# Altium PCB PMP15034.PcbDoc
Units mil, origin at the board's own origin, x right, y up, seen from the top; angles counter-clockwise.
Board outline 1900.05 x 1702.97 mil, 2 copper layers (Top Layer, Bottom Layer), stack 62 mil thick; 32 components, 19 nets, 82 pads, 10 vias.
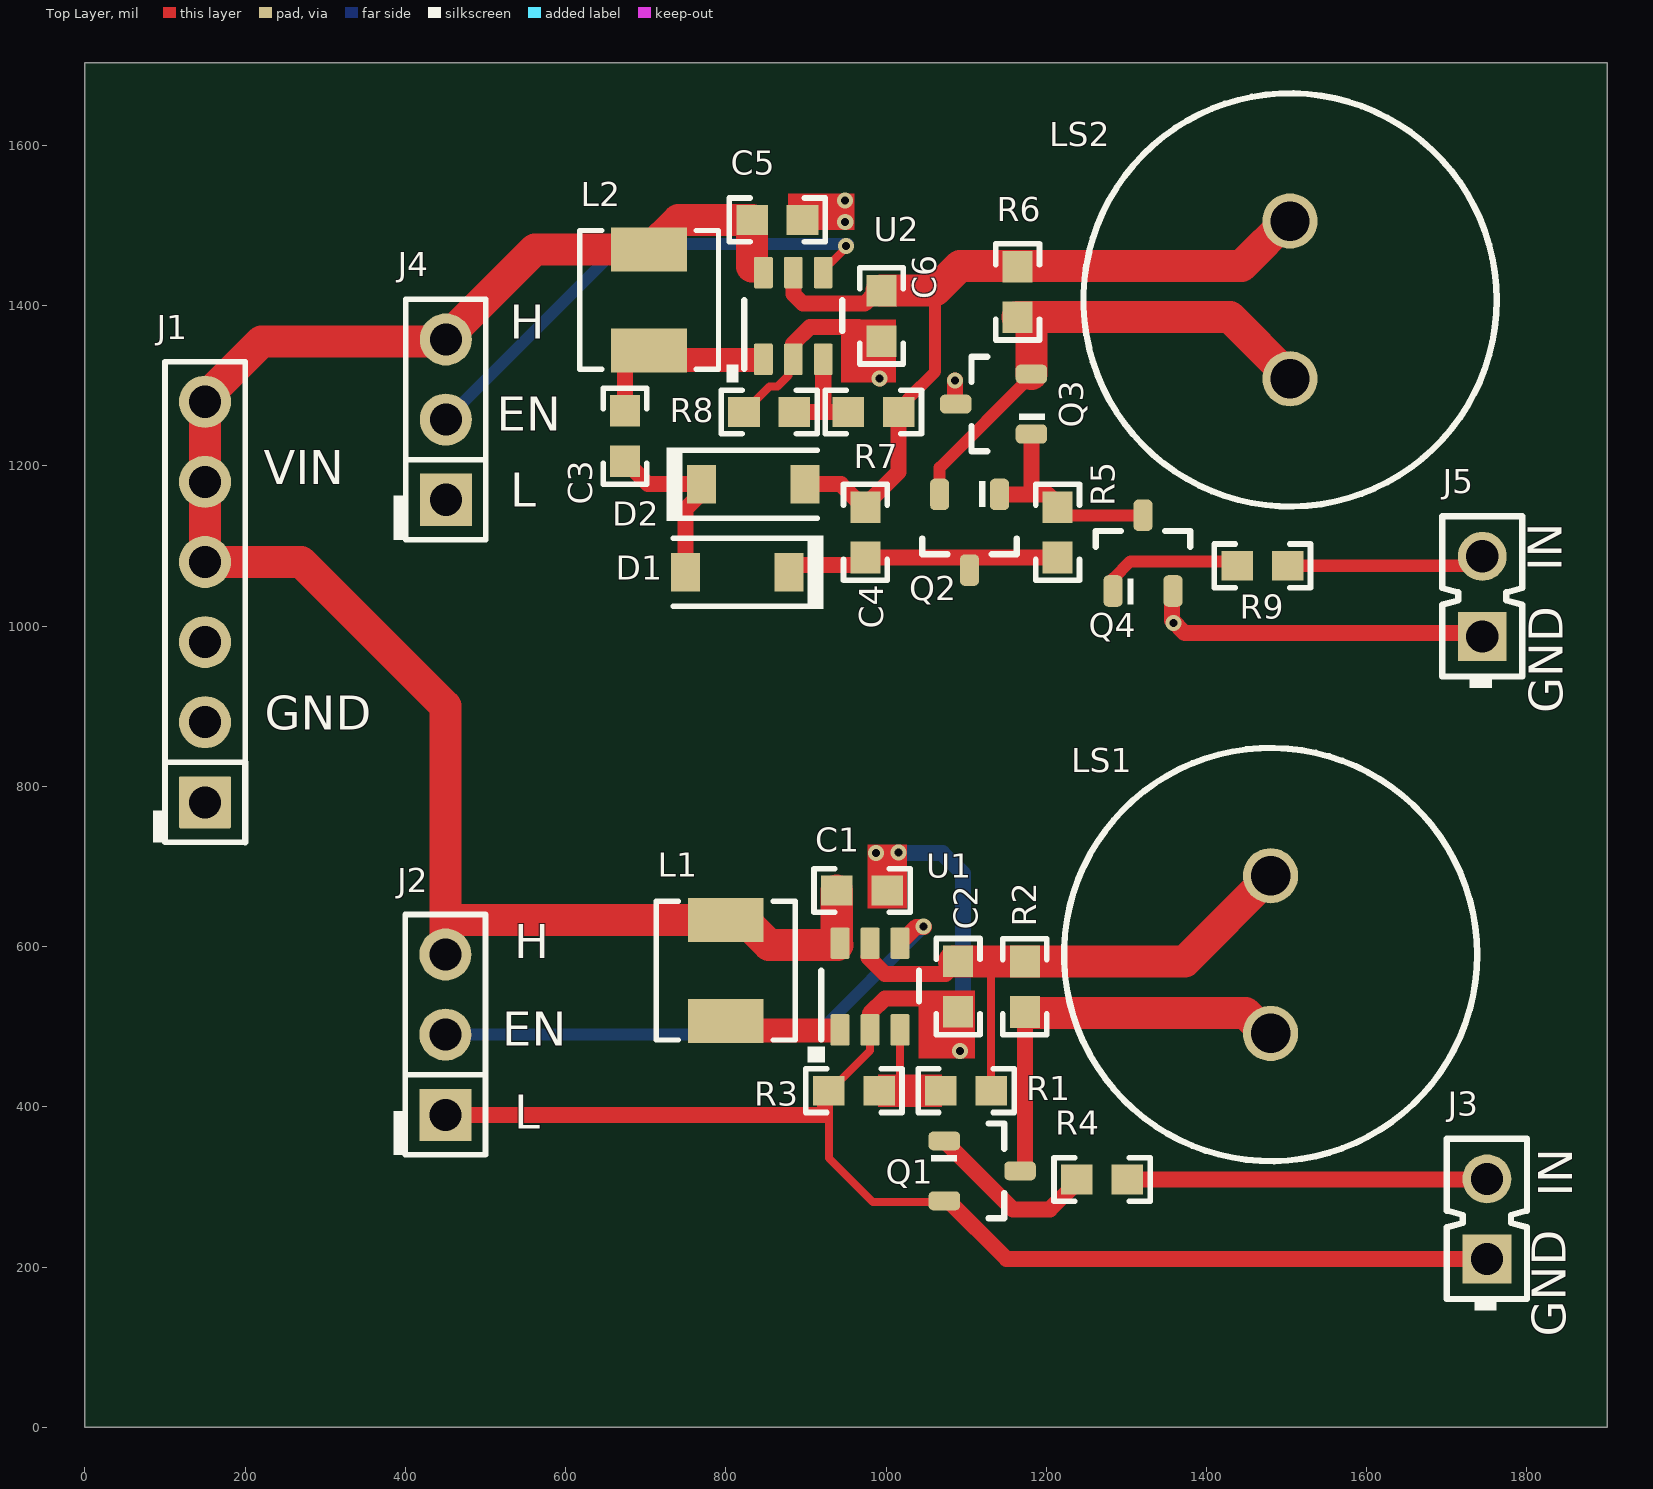
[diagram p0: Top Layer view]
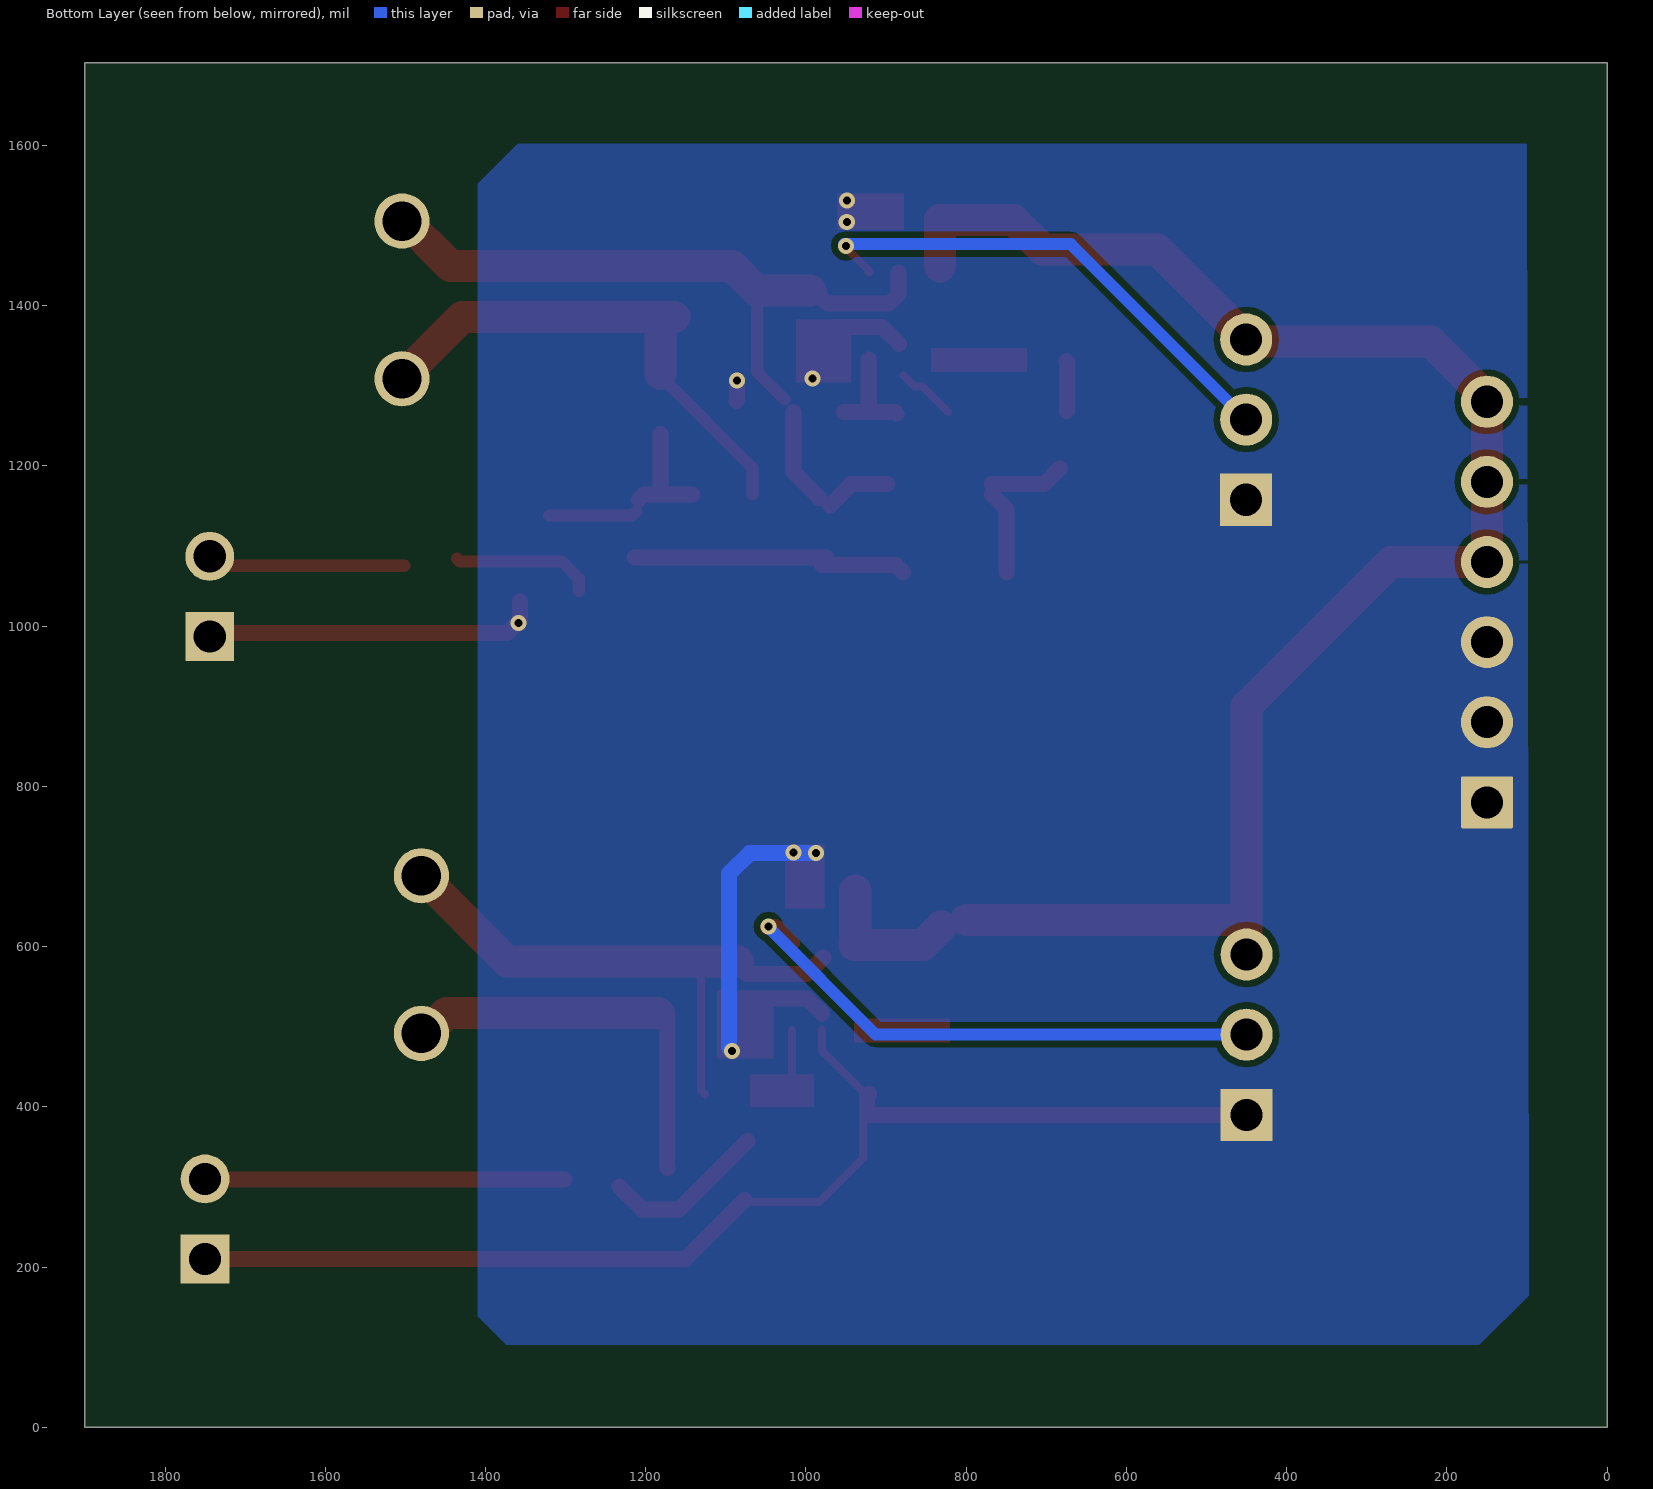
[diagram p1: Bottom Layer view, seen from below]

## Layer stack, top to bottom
Top Solder: solder mask 0.4, Solder Resist, Dk 3.5
Top Layer: signal copper 1.4
Dielectric1: core 59.2, FR-4, Dk 4.8
Bottom Layer: signal copper 1.4
Bottom Solder: solder mask 0.4, Solder Resist, Dk 3.5

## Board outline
0,0 1900,0 1899.96,1702.97 1900.05,1702.81 0.05,1702.81 0,1702.78

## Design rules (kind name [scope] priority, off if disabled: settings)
AcuteAngle [All] p1: minimum=4.50000000000000E+0001 checktracksonly=FALSE
AssemblyTestPointUsage [All] p1: valid=2
Clearance "U1 Clearance" [InComponent('U1')] p1: gap=4
Clearance "U2 Clearance" [InComponent('U2')] p2: gap=4
Clearance Clearance_BoardEdge_MountingHoles [OnCopper and InComponentClass('Mounting Holes') vs IsKeepOut] p3: gap=3.94
Clearance Clearance_BoardEdge_Poly [OnCopper and InPoly vs IsKeepOut] p4: gap=10
Clearance Clearance_BoardEdge [OnCopper and Not InComponentClass('Logo') and not InComponentClass('FiducialMark') and not InRegion(1000,500,4000,800) vs IsKeepOut] p5: gap=30
Clearance [All] p6: gap=8
ComponentClearance ComponentClearance_SHUNT [InComponentClass('Shunt')] p1: gap=0 collisioncheckmode=3 verticalgap=0 showdistances=FALSE
ComponentClearance ComponentClearance_Logo [All] p2: gap=10 collisioncheckmode=3 verticalgap=10 showdistances=FALSE
ComponentClearance ComponentClearance_ScrewToNut [(HasFootprint('NY PMS 440 0025 PH')) vs (HasFootprint('Keystone_1902C'))] p3: gap=5 collisioncheckmode=3 verticalgap=10 showdistances=FALSE
ComponentClearance ComponentClearance_MountingHoles [InComponentClass('Mounting Holes')] p4: gap=250 collisioncheckmode=3 verticalgap=100000 showdistances=FALSE
ComponentClearance ComponentClearance_SmallPassives [HasFootprint('0201*') or HasFootprint('0402*') or HasFootprint('0508') or HasFootprint('0603*') or HasFootprint('0612') or HasFootprint('0805*') or HasFootprint('0815*') or HasFootprint('0830*') or HasFootprint('1206*') or HasFootprint('1210*') or HasFootprint('1808*') or HasFootprint('1812*') or HasFootprint('1825*') or HasFootprint('2010*') or HasFootprint('2220*') or HasFootprint('2225*') or HasFootprint('2512*') or HasFootprint('2728*') or HasFootprint('3518*') vs HasFootprint('0201*') or HasFootprint('0402*') or HasFootprint('0508') or HasFootprint('0603*') or HasFootprint('0612') or HasFootprint('0805*') or HasFootprint('0815*') or HasFootprint('0830*') or HasFootprint('1206*') or HasFootprint('1210*') or HasFootprint('1808*') or HasFootprint('1812*') or HasFootprint('1825*') or HasFootprint('2010*') or HasFootprint('2220*') or HasFootprint('2225*') or HasFootprint('2512*') or HasFootprint('2728*') or HasFootprint('3518*')] p5: gap=20 collisioncheckmode=3 verticalgap=10 showdistances=FALSE
ComponentClearance ComponentClearance_THtoSMT [IsThruComponent vs IsSMTComponent] p6 off: gap=10 collisioncheckmode=3 verticalgap=100000 showdistances=FALSE
ComponentClearance ComponentClearance_THtoTH [IsThruComponent vs IsThruComponent] p7: gap=10.11 collisioncheckmode=3 verticalgap=100000 showdistances=FALSE
ComponentClearance [All] p8: gap=10 collisioncheckmode=3 verticalgap=10 showdistances=FALSE
DiffPairsRouting [All] p1: maxlimit=100 minlimit=10 mostfreqgap=10 toplayer_minwidth=15 toplayer_maxwidth=15 toplayer_prefwidth=15 bottomlayer_minwidth=15 bottomlayer_maxwidth=15 bottomlayer_prefwidth=15 maxuncoupledlength=1000
FabricationTestPointUsage TestPointUsage [All] p1: valid=2 allowmultiple=FALSE
FabricationTestpoint Testpoint [All] p1: side=3 testpointundercomponent=TRUE minsize=40 maxsize=100 preferedsize=60 minholesize=0 maxholesize=40 preferedholesize=32 testpointgrid=1 allowsidetop=TRUE allowsidebottom=TRUE usegrid=TRUE gridtolerance=0.01
FanoutControl Fanout_LCC [IsLCC] p1: bgadir=Out bgaviamode=Centered fanoutstyle=Auto fanoutdirection=Alternating viagrid=1 // Fanout_LCC (Default Rule)
FanoutControl Fanout_BGA [IsBGA] p2: bgadir=Out bgaviamode=Centered fanoutstyle=Auto fanoutdirection=Alternating viagrid=1 // Fanout_BGA (Default Rule)
FanoutControl Fanout_Default [All] p4: bgadir=Out bgaviamode=Centered fanoutstyle=Auto fanoutdirection=Alternating viagrid=1 // Fanout_Default (Default Rule)
FanoutControl Fanout_Small [(CompPinCount < 5)] p5: bgadir=Out bgaviamode=Centered fanoutstyle=Auto fanoutdirection=OutThenIn viagrid=1 // Fanout_Small (Default Rule)
HoleSize [All] p1: absolutevalues=TRUE maxlimit=180 minlimit=8 maxpercent=80.000 minpercent=20.000
HoleToHoleClearance [All] p1: gap=1 allowstackedmicrovias=TRUE
MinimumAnnularRing MinimumAnnularRing_small [TouchesRoom('BGA_Room')] p1: minimumring=2.8
MinimumAnnularRing [All] p2: minimumring=5
MinimumSolderMaskSliver U2 [InComponent('U1')] p1: minsoldermaskwidth=3
MinimumSolderMaskSliver "SW PIN" [InNet('SW')] p2: minsoldermaskwidth=10
MinimumSolderMaskSliver U1 [InComponent('U2')] p3: minsoldermaskwidth=3
MinimumSolderMaskSliver SilkscreenOverComponentPads [All] p4: minsoldermaskwidth=5
MinimumSolderMaskSliver MinimumSolderMaskSliver_Logo [InComponentClass('Logo') vs InComponentClass('Logo')] p5: minsoldermaskwidth=0.7
MinimumSolderMaskSliver [All] p6: minsoldermaskwidth=4
PlaneClearance [All] p1: clearance=10
PlaneConnect [All] p1: planeconnectstyle=Direct reliefexpansion=10 reliefentries=4 reliefconductorwidth=10 reliefairgap=10
PolygonConnect PolygonConnect-TH-Relief [IsPoly vs (IsThruPin)  And Not (InComponent('U3'))  And Not (InComponent('U4'))] p1: connectstyle=Direct reliefconductorwidth=20 reliefentries=4 polygonreliefangle="90 Angle" airgapwidth=10
PolygonConnect PolygonConnect-DirectConn [All] p2: connectstyle=Direct reliefconductorwidth=10 reliefentries=4 polygonreliefangle="90 Angle" airgapwidth=10
RoutingVias [All] p1: holewidth=10 width=22 viastyle="Through Hole" minholewidth=4 minwidth=10 maxholewidth=50 maxwidth=100
SMDToCorner [All] p1: distance=0
SilkToBoardRegionClearance [Not ((IsComment or IsDesignator) And (Hide <> 'False')) and not InRegion(1000,500,4000,800)] p1:
SilkToSilkClearance "Pb Free Logo" [(HasFootprint('Pb-Free_Overlay_Medium') OR HasFootprint('Pb-Free_Overlay_Small')) vs (HasFootprint('Pb-Free_Overlay_Medium') OR HasFootprint('Pb-Free_Overlay_Small'))] p1: silktosilkclearance=0
SilkToSilkClearance [All] p2: silktosilkclearance=3
SilkToSolderMaskClearance [IsPad] p1: minsilkscreentomaskgap=4 clearancetoexposedcopper=TRUE
SolderMaskExpansion [All] p1: expansion=1
Width [All] p1: maxlimit=100 minlimit=6 preferedwidth=10 checkconnectedcopper=TRUE
13 further rules are at their usual default settings.

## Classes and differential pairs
component class Header: J1 J2 J3 J4 J5

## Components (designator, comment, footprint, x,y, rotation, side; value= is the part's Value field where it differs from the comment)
C1 "GRM188R60J475KE19D" 0603 970,670 r0 top
C2 "GRM188R6YA475KE15D" 0603 1090,550 r270 top
C3 "GRM188R71H104KA93D" 0603 674.22,1237.06 r270 top
C4 "GRM188R6YA475KE15D" 0603 974.22,1117.06 r90 top
C5 "GRM188R60J475KE19D" 0603 864.22,1507.06 r0 top
C6 "GRM188R6YA475KE15D" 0603 994.22,1387.06 r270 top
D1 "1N4148W-7-F" SOD-123 814.22,1067.06 r180 top
D2 "1N4148W-7-F" SOD-123 834.22,1177.06 r0 top
J1 "TSW-106-07-G-S" TSW-106-07-G-S 150,1030 r90 top
J2 "TSW-103-07-G-S" TSW-103-07-G-S 450,490 r90 top
J3 "TSW-102-07-T-S" Samtec_TSW-102-07-T-S 1750,260 r90 top
J4 "TSW-103-07-G-S" TSW-103-07-G-S 450.49,1257.68 r90 top
J5 "TSW-102-07-T-S" Samtec_TSW-102-07-T-S 1744.22,1037.06 r90 top
L1 "FDSD0420-H-100M" FDSD0420 800,570 r270 top
L2 "FDSD0420-H-100M" FDSD0420 704.22,1407.06 r270 top
LS1 "PKM13EPYH4002-B0" MuRata_PKM13 1480,590 r270 top
LS2 "PKM13EPYH4002-B0" MuRata_PKM13 1504.22,1407.06 r90 top
Q1 "MMBT3904-7-F" SOT-23 1120,320 r0 top
Q2 "MMBT3904-7-F" SOT-23 1104.22,1117.06 r270 top
Q3 "MMBT3906-7-F" SOT-23 1134.22,1277.06 r180 top
Q4 "MMBT3904-7-F" SOT-23 1320.78,1091.03 r90 top
R1 "CRCW06031M00FKEA" 0603 1100,420 r0 top
R2 "CRCW06033K01FKEA" 0603 1173.18,549.8 r90 top
R3 "CRCW060329K4FKEA" 0603 960,420 r0 top
R4 "CRCW060310K0FKEA" 0603 1269.65,309.33 r0 top
R5 "CRCW060310K0FKEA" 0603 1214.22,1117.06 r90 top
R6 "CRCW06031M00FKEA" 0603 1164.22,1417.06 r270 top
R7 "CRCW06031M00FKEA" 0603 984.22,1267.06 r0 top
R8 "CRCW060356K2FKEA" 0603 854.22,1267.06 r0 top
R9 "CRCW060310K0FKEA" 0603 1469.81,1075.28 r180 top
U1 "TLV61046ADBVR" DBV0006A_N 980,550 r90 top
U2 "TLV61046ADBVR" DBV0006A_N 884.22,1387.06 r90 top

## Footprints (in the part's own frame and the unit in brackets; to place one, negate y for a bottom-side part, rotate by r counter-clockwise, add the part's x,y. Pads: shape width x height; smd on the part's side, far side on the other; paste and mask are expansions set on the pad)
0603 [mm] "0603 from SM-752 data"
  rect 1x0.95 smd: 1(-0.8,0) 2(0.8,0)
  silkscreen extent -1.52,-0.69 1.52,0.69, body extent -0.87,-0.47 0.87,0.47, height 1
DBV0006A_N [mm] "SOT23, 6-Leads, Body 2.9x1.6mm, Pitch 0.95mm, Lead Span 2.8mm, IPC Medium Density"
  rrect17% 1x0.6 smd: 1(-1.375,0.95) 2(-1.375,0) 3(-1.375,-0.95) 4(1.375,-0.95) 5(1.375,0) 6(1.375,0.95)
  silkscreen extent -1.68,-1.55 0.5,1.55, body extent -1.42,-1.46 1.42,1.46, height 1.12
FDSD0420 [mm] "SMD, 2-Leads, Body 4.2x4.2mm"
  rect 1.4x2.4 smd: 1(-1.6,0) 2(1.6,0)
  silkscreen extent -2.2,-2.2 2.2,2.2, body extent -2.1,-2.1 2.1,2.1, height 2
MuRata_PKM13 [mm] "TH, 2-Leads, Dia 12.6mm, Pitch 5mm"
  round 1.75 hole 1.25: 1(-2.5,0) 2(2.5,0)
  silkscreen extent -6.55,-6.55 6.55,6.55, body extent -6.55,-6.55 6.55,6.55, height 7.4
Samtec_TSW-102-07-T-S [mm] "Header, 2.54 mm, 2x1, Tin, TH"
  rect 1.55x1.55 hole 1.02: 1(-1.27,0)
  round 1.55 hole 1.02: 2(1.27,0)
  silkscreen extent -2.9,-1.27 2.54,1.27, body extent -2.54,-1.27 2.54,1.27, height 8.38
SOD-123 [mm] "On Semi recommended land pattern"
  rect 0.915x1.22 smd: 1(-1.637,0) 2(1.637,0)
  silkscreen extent -2.74,-1.17 2.03,1.17, body extent -1.93,-0.9 1.93,0.9, height 1.35
SOT-23 [mm] "SOT23, 3-Leads, Body 2.9x1.3mm, Pitch 0.95mm, Lead Span 2.5mm, IPC Medium Density"
  rrect50% 1x0.6 smd: 1(-1.2,0.95) 2(-1.2,-0.95) 3(1.2,0)
  silkscreen extent -1.63,-1.5 0.7,1.5, body extent -1.16,-1.45 1.21,1.45, height 1
TSW-103-07-G-S [mm] "Samtec 100mil, 1x3, 230 mil above insulator"
  rect 1.65x1.65 hole 1.016: 1(-2.54,0)
  round 1.65 hole 1.016: 2(0,0) 3(2.54,0)
  silkscreen extent -3.81,-1.27 3.81,1.65, body extent -3.81,-1.27 3.81,1.27, height 8.38
TSW-106-07-G-S [mm] "Samtec 100mil, 1x6, 230 mil above insulator"
  rrect6% 1.65x1.65 hole 1.016: 1(-6.35,0)
  round 1.65 hole 1.016: 2(-3.81,0) 3(-1.27,0) 4(1.27,0) 5(3.81,0) 6(6.35,0)
  silkscreen extent -7.62,-1.27 7.62,1.65, body extent -7.62,-1.27 7.62,1.27, height 8.38

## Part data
C1 C5: "CAP, CERM, 4.7 µF, 6.3 V, +/- 10%, X5R, 0603"
C2 C4 C6: "CAP, CERM, 4.7 µF, 35 V, +/- 10%, X5R, 0603"
C3: "CAP, CERM, 0.1 µF, 50 V, +/- 10%, X7R, 0603"
D1 D2: "Diode, Ultrafast, 100 V, 0.15 A, SOD-123"
J1: "Header, 100mil, 6x1, Gold, TH"
J2 J4: "Header, 100mil, 3x1, Gold, TH"
J3 J5: "Header, 2.54 mm, 2x1, Tin, TH"
L1 L2: "Inductor, Shielded, Powdered Iron, 10 µH, 2 A, 0.2 ohm, SMD"
LS1 LS2: "Buzzer, 4 kHz, 12.6mm Dia, TH"
Q1 Q2 Q4: library part "MMBT3904-7-F, Diodes Inc.", "Transistor, NPN, 40 V, 0.2 A, SOT-23"
Q3: library part "MMBT3906-7-F, Diodes Inc.", "Transistor, PNP, 40 V, 0.2 A, SOT-23"
R1 R6 R7: "RES, 1.00 M, 1%, 0.1 W, 0603"
R2: "RES, 3.01 k, 1%, 0.1 W, 0603"
R3: "RES, 29.4 k, 1%, 0.1 W, 0603"
R4 R5 R9: "RES, 10.0 k, 1%, 0.1 W, 0603"
R8: "RES, 56.2 k, 1%, 0.1 W, 0603"
U1 U2: "28-V Output Voltage Boost Converter with Power Diode and Isolation Switch, DBV0006A (SOT-6)"

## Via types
v1: diameter 20, hole 10, Top Layer to Bottom Layer, 10 vias

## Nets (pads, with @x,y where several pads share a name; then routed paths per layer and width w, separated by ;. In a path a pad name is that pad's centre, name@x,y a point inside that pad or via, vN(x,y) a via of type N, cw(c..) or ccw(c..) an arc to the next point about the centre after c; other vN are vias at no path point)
15V: C4.2 C6.1 D2.2 LS2.2 R6.1 R7.2 U2.5 | length 1040.5
  Top Layer w15: R7.2@1026.57,1282.72 1061.33,1317.48 1061.33,1418.56
  Top Layer w20: U2.5 884.22,1414.48 896.36,1402.34 973.21,1402.34 C6.1@985.47,1414.6 ; D2.2 943.58,1177.06 C4.2@970.25,1150.38 ; C4.2@983.44,1160.1 1015.72,1192.38 R7.2
  Top Layer w40: C6.1 1061.33,1418.56 1092.11,1449.34 1443.78,1449.34 LS2.2@1505.23,1510.8
28V: C2.1 LS1.1 R1.2 R2.2 U1.5 | length 803
  Top Layer w10: R1.2@1126.14,415.58 1131.21,420.66 1131.21,581.5
  Top Layer w20: U1.5@978.19,586.1 998.81,565.48 1073.98,565.48 C2.1 1131.21,581.5 R2.2@1160,581.5
  Top Layer w40: C2.1@1084.94,581.29 1372.84,581.5 LS1.1@1478.99,687.65
30V: C4.1 D1.1 Q2.3 R5.1 | length 345.1
  Top Layer w20: D1.1 887.8,1076.17 C4.1@979.99,1076.17 ; C4.1 R5.1
ENA: J2.2 U1.4 | length 693.6
  Top Layer w20: U1.4 1037.79,624.52 v1@1047.65,624.52
  Bottom Layer w15: J2.2 912.88,490 v1@1048.64,625.76
  other v1: 1046.81,624.94
ENB: J4.2 U2.4 | length 637.9
  Top Layer w10: U2.4 921.62,1443.86 v1@951.7,1473.94
  Bottom Layer w15: J4.2 669.4,1476.59 v1@952.5,1476.59
  other v1: 950.05,1474.43
FBA: R1.1 R3.2 U1.3 | length 83.3
  Top Layer w10: 1017.4,412.58 U1.3
FBB: R7.1 R8.2 U2.3 | length 129.7
  Top Layer w20: R8.2@886.84,1265.57 888.33,1267.06 R7.1 ; 921.62,1269.77 U2.3
GND: C1.2 C2.2 C5.2 C6.2 J1.1 J1.2 J1.3 J2.1 J3.1 J4.1 J5.1 Q1.2 Q3.3 Q4.2 R3.1 R8.1 U1.2 U2.2 | length 2737.9
  Top Layer w10: R8.1 854.71,1299.05 864.68,1299.05 878.43,1312.8 ; U1.2 980,470 930,420 R3.1 928.5,336.12 983.5,281.12 Q1.2@1066.1,281.12
  Top Layer w20: J2.1 923.74,390 923.74,413.45 R3.1@921.53,415.66 ; U2.2@883.88,1352.2 905.12,1373.44 965.54,1373.44 983.41,1355.57 C6.2 994.22,1310.63 v1@992.72,1309.13 ; 979.91,516.51 998.81,535.41 1065.25,535.41 1082.15,518.5 C2.2 ; Q1.2@1076.54,283.83 1150.37,210 J3.1 ; v1(1085.92,1306.6) 1085.92,1282.08 Q3.3@1086.8,1281.2 ; C2.2@1090,516.35 1092.1,514.25 v1(1092.1,469.81) ; Q4.2@1357.18,1030.76 1357.03,1030.62 1357.03,1006.97 1372.84,991.16 J5.1@1734.9,991.16
  Bottom Layer w20: v1(987.51,716.71) 1070.37,716.71 1096.15,690.93 v1@1096.15,473.69
  other v1: 1015.74,717.59 1358.59,1003.8 991.76,1309.13 949.08,1504.44 948.81,1531.46
NetC3_1: C3.1 L2.2 U2.1 | length 62.9
  Top Layer w20: C3.1 674.22,1330.23 L2.2@675.08,1331.09
NetC3_2: C3.2 D1.2 D2.1 | length 197.1
  Top Layer w20: C3.2@683.05,1196.91 702.9,1177.06 D2.1@767.53,1177.06 ; D1.2 749.75,1146.28 D2.1@767.53,1164.06
NetJ3_2: J3.2 R4.2 | length 465.3
  Top Layer w20: R4.2 J3.2@1766.45,309.33
NetJ5_2: J5.2 R9.1 | length 255.5
  Top Layer w15: R9.1 J5.2@1756.82,1075.28
NetL1_2: L1.2 U1.1
NetLS1_2: LS1.2 Q1.3 R2.1 | length 498.1
  Top Layer w20: Q1.3@1173.1,323.84 1173.18,323.93 R2.1
  Top Layer w40: R2.1@1183.78,517.04 1448.48,517.04 LS1.2@1476.01,489.51
NetLS2_1: LS2.1 Q2.2 Q3.2 R6.2 | length 629.4
  Top Layer w15: Q2.2 1066.82,1197.65 Q3.2@1182.19,1313.03
  Top Layer w40: R6.2 1429.4,1385.57 LS2.1@1502.04,1312.92 ; R6.2@1177.82,1377.97 1181.46,1374.32 Q3.2
NetQ1_1: Q1.1 R4.1 | length 207.2
  Top Layer w20: Q1.1 1158.22,271.94 1204.35,271.94 R4.1@1232.81,300.4
NetQ2_1: Q2.1 Q3.1 Q4.3 R5.2 | length 253.4
  Top Layer w15: R5.2@1211.64,1143.23 1216.6,1138.27 Q4.3
  Top Layer w20: Q2.1 1202.02,1164.31 R5.2@1208.12,1158.21 ; 1181.46,1166.46 Q3.1
NetQ4_1: Q4.1 R9.2 | length 177.8
  Top Layer w15: Q4.1 1283.38,1059.1 1305,1080.72 1432.2,1080.72 R9.2@1435.53,1084.05
VIN: C1.1 C5.1 J1.4 J1.5 J1.6 J2.3 J4.3 L1.1 L2.1 U1.6 U2.6 | length 2252.5
  Top Layer w40: J1.6@150,1290 J1.6 J1.5 J1.4 270,1080 450,900 J2.3 ; J1.6@153.03,1287.81 220.44,1355.21 446.78,1355.21 561.63,1470.05 L2.1 741.23,1507.06 C5.1 832.72,1448.56 ; 457.01,632.99 L1.1 ; L1.1@831.27,624.76 853.9,602.13 939.53,602.13 938.5,603.15 C1.1

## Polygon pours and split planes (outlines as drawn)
GND on Bottom Layer "BOTTOM_LAYER_GND_P000" (solid, remove dead copper, pour order 0): 100.25,1601.79 1359.79,1601.79 1409.6,1551.98 1409.6,138.27 1374.02,102.69 159.55,102.69 97.88,164.36

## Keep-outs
Keep-Out Layer:
  text ".Layer_Name" at 577,-858.49 h60

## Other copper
Top Layer:
  rectangle net GND: 943.69,1303.93 1012.38,1382.85
  rectangle net GND: 1040.8,460.03 1111.31,545.29
  rectangle net GND: 976.57,647.46 1026.04,727.12
  rectangle net FBA: 990,400 1070,440
  rectangle net NetL1_2: 820,480 940,510
  rectangle net NetC3_1: 724.22,1317.06 844.22,1347.06
  rectangle net GND: 877.8,1494.51 960.61,1540.08
  text ".Layer_Name" at 577,-858.49 h60
Bottom Layer:
  text ".Layer_Name" at 577,-858.49 h60

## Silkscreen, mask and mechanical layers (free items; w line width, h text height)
Top Overlay:
  rectangle: 800.92,1304.21 815.72,1326.7
  rectangle: 902.21,455.55 923.7,474.94
  text "H" at 530.29,1344.47 h72.83
  text "EN" at 514.17,1229.33 h72.83
  text "VIN" at 223.54,1162.47 h72.83
  text "L" at 531.14,1135.12 h72.83
  text "IN" at 1858.03,1068.21 h72.83 r90
  text "GND" at 1858.79,890.94 h72.83 r90
  text "GND" at 224.47,856.05 h72.83
  text "H" at 536.2,571.25 h72.83
  text "EN" at 521.01,461.51 h72.83
  text "L" at 536.2,358.53 h72.83
  text "IN" at 1871.07,287.78 h72.83 r90
  text "GND" at 1862.63,112.81 h72.83 r90
  text ".Layer_Name" at 577,-858.49 h60
Bottom Overlay:
  text ".Layer_Name" at 577,-858.49 h60
Top Paste:
  text ".Layer_Name" at 577,-858.49 h60
Bottom Paste:
  text ".Layer_Name" at 577,-858.49 h60
Top Solder:
  text ".Layer_Name" at 577,-858.49 h60
  text ".Layer_Name" at 577,-858.49 h60
Bottom Solder:
  text ".Layer_Name" at 577,-858.49 h60
Drill Guide:
  text ".Layer_Name" at 577,-858.49 h60
M1 Board Outline:
  lines w10: 0,0 1900,0 1899.96,1702.97 ; 0,1702.78 0.18,0.42 ; 0.05,1702.81 1900.05,1702.81
  text ".Layer_Name" at 577,-858.49 h60
M2 Board Dimensions:
  rectangle: 0,-275 125,-150
  rectangle: 125,-400 500,-275
  lines w7: 0,-275 1000,-275 ; 125,-400 125,-150 ; 250,-400 250,-150 ; 500,-400 500,-150 ; 750,-400 750,-150 ; 0,-400 1000,-400 1000,-150 0,-150 0,-400
  text ".Layer_Name" at 577,-858.49 h60
M3 3D STEP Top:
  text ".Layer_Name" at 577,-858.49 h60
M4 3D STEP Bottom:
  text ".Layer_Name" at 577,-858.49 h60
M5 Assembly Top:
  lines w10: -292,-930.17 6308,-930.17 ; -292,-726.83 6310,-726.83 ; -292,-523.5 -292,-1133.5 3713,-1133.5 6310,-1133.5 6310,-523.5 -291.5,-523.5 -291.5,-1133.5 1284,-1133.5 ; 2173,-1133.5 2173,-523.5 ; 3440,-726.83 3440,-523.5 ; 4280,-726.83 4280,-523.5 ; 4902,-1140 4902,-937.17
  text "COMPONENTS MARKED 'DNP' SHOULD NOT BE POPULATED." at 1153.5,-318.5 h60
  text "ASSEMBLY VARIANT:" at 1153,-434 h60
  text ".VariantName" at 2189,-434 h60
  text "PCB VIEWED FROM TOP SIDE" at -228.5,-655.67 h60
  text "BOARD #:" at 2248,-655.67 h60
  text ".PRJ_Number" at 2793.5,-655.67 h60
  text "REV:" at 3638,-655.67 h60
  text ".PCB_Rev" at 3929.5,-655.67 h60
  text "SVN REV:" at 4476,-655.67 h60
  text ".VersionControl_RevNumber" at 4982,-655.67 h60
  text "TID #:" at 2248,-859 h60
  text ".TID" at 2793.5,-859 h60
  text "PLOT NAME =" at -228.5,-1064.34 h60
  text ".plot_File_Name" at 577,-1064.34 h60
  text "GENERATED    :" at 2250,-1064.34 h60
  text ".Print_Date" at 3119.5,-1064.34 h60
  text ".Print_Time" at 3848.5,-1064.34 h60
  text "TEXAS INSTRUMENTS" at 5113,-1064.34 h60
M6 Assembly Bottom:
  lines w10: -292.5,-727.33 6309.5,-727.33 ; -290.5,-930.67 6309.5,-930.67 ; 1115.5,-1140.5 1115.5,-937.67 ; 1737.5,-727.33 1737.5,-524 ; 2577.5,-727.33 2577.5,-524 ; 3844.5,-1134 3844.5,-524 ; 4733.5,-1134 6309,-1134 6309,-524 -292.5,-524 -292.5,-1134 2304.5,-1134 6309.5,-1134 6309.5,-524
  text "COMPONENTS MARKED 'DNP' SHOULD NOT BE POPULATED." at 6102,-318 h60
  text ".VariantName" at 5058,-434 h60
  text "ASSEMBLY VARIANT:" at 6097,-434 h60
  text ".VersionControl_RevNumber" at 1035.5,-656.17 h60
  text "SVN REV:" at 1541.5,-656.17 h60
  text ".PCB_Rev" at 2088,-656.17 h60
  text "REV:" at 2379.5,-656.17 h60
  text ".PRJ_Number" at 3224,-656.17 h60
  text "BOARD #:" at 3769.5,-656.17 h60
  text "PCB VIEWED FROM BOTTOM SIDE" at 6246,-656.17 h60
  text ".TID" at 3224,-859.5 h60
  text "TID #:" at 3769.5,-859.5 h60
  text "TEXAS INSTRUMENTS" at 904.5,-1064.84 h60
  text ".Print_Time" at 2169,-1064.84 h60
  text ".Print_Date" at 2898,-1064.84 h60
  text "GENERATED    :" at 3767.5,-1064.84 h60
  text ".plot_File_Name" at 5440.5,-1064.84 h60
  text "PLOT NAME =" at 6246,-1064.84 h60
M9 Title Sheet:
  drawing of 57 lines, arcs and shapes, not listed
  text "1" at 739.84,8036.5 h70
  text "2" at 3235.5,8036.5 h70
  text "3" at 5724.84,8036.5 h70
  text "4" at 8231.51,8036.5 h70
  text "5" at 10730.5,8036.5 h70
  text "6" at 13235.5,8036.5 h70
  text "A" at -416.5,6893.5 h70
  text "A" at 14383.5,6893.5 h70
  text "B" at -416.5,4513.5 h70
  text "B" at 14383.5,4513.5 h70
  text "C" at -416.5,2138.5 h70
  text "C" at 14383.5,2138.5 h70
  text "PROJECT TITLE:" at 11343.5,277.5 h45
  text ".PRJ_Title" at 11393.5,144.17 h70
  text "DESIGNED FOR:" at 11343.5,-23.5 h45
  text ".PRJ_Customer" at 11393.5,-163.5 h70
  text "D" at -416.5,-231.5 h70
  text "D" at 14383.5,-231.5 h70
  text "FILE NAME:" at 11343.5,-323.5 h45
  text ".PCB_File_Name_No_Path" at 11393.5,-443.5 h70
  text "Texas Instruments (TI) and/or its licensors do not warrant the accuracy or completeness of this specification" at 6374,-605.34 h45
  text "ENGINEER:" at 11343.5,-613.5 h45
  text "LAYOUT BY:" at 12848.5,-613.5 h45
  text "or any information contained therein. TI and/or its licensors do not warrant that this design will meet" at 6329.01,-718 h45
  text ".PRJ_Engineer" at 11393.5,-768.49 h70
  text ".PCB_Layout" at 12899,-768.49 h70
  text "the specifications, will be suitable for your application or fit for any particular purpose, or will operate in" at 6329.01,-830.67 h45
  text ".Layer_Name" at 577,-858.49 h60
  text "ALTIUM DESIGNER VERSION:" at 12848.5,-923.5 h45
  text "an implementation. TI and/or its licensors do not warrant that the design is production worthy. You should" at 6329.01,-943.33 h45
  text "completely validate and test your design implementation to confirm the system functionality for your application." at 6374,-1056 h45
  text ".print_Scale" at 11393.5,-1056.83 h70
  text ".Application_BuildNumber" at 12899,-1056.83 h70
  text "1" at 739.84,-1263.5 h70
  text "2" at 3235.5,-1263.5 h70
  text "3" at 5724.84,-1263.5 h70
  text "4" at 8231.51,-1263.5 h70
  text "5" at 10730.5,-1263.5 h70
  text "6" at 13235.5,-1263.5 h70
M10 Fab Notes:
  drawing of 173 lines, arcs and shapes, not listed
  text "DESIGN INFORMATION" at 12378.02,6201 h60
  text "MIN. TRACK WIDTH:" at 11733.46,6021 h60
  text "8" at 12829.7,6021 h60
  text "MIL" at 12984.46,6021 h60
  text "MIN. CLEARANCE:" at 11733.46,5889 h60
  text "0.2" at 12769.7,5889 h60
  text "mm" at 12984.46,5889 h60
  text "MIN. VIA PAD SIZE:" at 11733.46,5757 h60
  text "24" at 12799.71,5757 h60
  text "MIL" at 12984.46,5757 h60
  text "0.05mm (2MIL)" at 12428.46,5615.29 h60
  text "MINIMUM ANNULAR RING" at 11404.23,5611 h60
  text "EXTERNAL" at 13136.46,5611 h60
  text "PER" at 11604.23,5493 h60
  text "IPC-D-275 CLASS 2 LEVEL C" at 11824.23,5493 h60
  text "MIL, HOLES" at 13312.46,5380.71 h60
  text "+/-" at 12920,5380 h60
  text "+/-" at 13774,5380 h60
  text "REGISTRATION TOLERANCES:" at 11404.23,5375 h60
  text "METAL" at 12604,5375 h60
  text "5" at 13180.2,5375 h60
  text "3" at 14013.2,5375 h60
  text "MIL" at 14129.46,5375 h60
  text "+/-" at 13774,5262 h60
  text "HOLE SIZE TOLERANCE (UNLESS OTHERWISE SPECIFIED):" at 11404.23,5257 h60
  text "3" at 14013.2,5257 h60
  text "MIL" at 14129.46,5257 h60
  text "MATERIAL:" at 11329.46,5047.54 h60
  text "FR-4 High Tg" at 12315.9,4907.21 h60
  text "FR-408" at 11750.46,4898.64 h60
  text "OTHER" at 13238.46,4898.64 h60
  text "X" at 12161,4895 h60
  text "62 MIL (1.6mm) +/-10%" at 12070.56,4735.92 h60
  text "THICKNESS:" at 11404.23,4731.64 h60
  text "X" at 11942.4,4731.64 h60
  text "OTHER" at 13355.46,4731.64 h60
  text "TOLERANCE:" at 11404.23,4573.64 h60
  text "X" at 12243.53,4573.64 h60
  text "ANSI IPC-6012 TYPE 3 CLASS 2" at 12430.48,4573.64 h60
  text "OTHER +/-" at 12430.46,4417.64 h60
  text "BOW & TWIST:" at 11404.23,4260.64 h60
  text "X" at 12243.53,4260.64 h60
  text "ANSI IPC-6012 TYPE 3 CLASS 2" at 12430.48,4260.64 h60
  text "OTHER +/-" at 12430.46,4102.13 h60
  text "DRILLING:" at 11329.46,3963.64 h60
  text "REFERENCE:" at 11404.23,3846.64 h60
  text "X" at 12052.46,3846.64 h60
  text "AS SHOWN" at 12239.46,3846.64 h60
  text "X" at 12953.46,3846.64 h60
  text "NC_DRILL FILES" at 13090.46,3846.64 h60
  text "PTH COPPER THICKNESS:" at 11404.23,3688.64 h60
  text "X" at 12534.46,3688.64 h60
  text "20-30 um" at 12671.46,3688.64 h60
  text "OTHER" at 13388.46,3688.64 h60
  text "BOARD FINISH:" at 11329.46,3529.64 h60
  text "SILKSCREEN:" at 11484.68,3411.64 h60
  text "X" at 12433.46,3411.64 h60
  text "TOP" at 12559.46,3411.64 h60
  text "X" at 12943.46,3411.64 h60
  text "BOTTOM" at 13070.46,3411.64 h60
  text "SILKSCREEN COLOR:" at 11484.68,3244.64 h60
  text "X" at 12432.42,3244.64 h60
  text "WHITE" at 12559.46,3244.64 h60
  text "OTHER" at 13070.46,3244.64 h60
  text "X" at 12563.42,3085.44 h60
  text "GREEN" at 12690.46,3085.44 h60
  text "OTHER" at 13308.46,3085.44 h60
  text "SOLDER RESIST COLOR:" at 11484.68,3074.64 h60
  text "X" at 12563.42,2915.44 h60
  text "MATTE" at 12690.46,2915.44 h60
  text "SEMI-GLOSS" at 13308,2914.8 h60
  text "IMMERSION GOLD (ENIG)" at 12390.46,2726.92 h60
  text "ENEPIG" at 13728,2723.64 h60
  text "SURFACE FINISH:" at 11329.46,2722.64 h60
  text "X" at 12203.51,2722.64 h60
  text "IMM. TIN/SILVER OR EQUIV" at 11659,2565.64 h60
  text "OTHER" at 13090.46,2565.64 h60
  text "ARRAY/PANEL:" at 11329.46,2386.64 h60
  text "CUT AND TRIM PER M1 BOARD OUTLINE" at 12390.46,2382.35 h60
  text "N.C. ROUTE" at 12390.46,2230.64 h60
  text "X" at 13069.46,2230.64 h60
  text "V. SCORE" at 13256.46,2230.64 h60
  text "CERTIFICATION:" at 11329.46,2093.64 h60
  text "MATERIALS AND WORKMANSHIP FOR ALL PCBS" at 12054.46,2093.64 h60
  text "TO MEET OR EXCEED THE REQUIREMENTS OF:" at 12054.46,1995.64 h60
  text "X" at 11680.96,1859.13 h60
  text "ANSI IPC-A-600F CLASS ->" at 11819.96,1859.13 h60
  text "X" at 13459.02,1859.13 h60
  text "2" at 13577.96,1859.14 h60
  text "1" at 13262.96,1857.64 h60
  text "3" at 13931.96,1857.64 h60
  text "X" at 12495.02,1699.64 h60
  text "RoHS" at 12631.96,1699.64 h60
  text "OTHER" at 13276.36,1699.64 h60
  text "PER ORDER" at 13673.42,1699.64 h60
  text "ALL BOARDS MUST MEET OR EXCEED UL94-V0 REQUIREMENTS." at 11357,1534 h60
  text "PCB MUST BEAR THE UL94V-0 UL REGISTERED MATERIAL ID NUMBER" at 11357,1414 h60
  text "ADDITIONAL REQUIREMENTS:" at 11329.46,1240.64 h60
  text "MICROSECTION:" at 11404.23,1125.64 h60
  text "YES" at 12309.96,1125.64 h60
  text "REQUIRED" at 13171.46,969.49 h60
  text "BARE BOARD ELEC. TEST:" at 11404.23,966.64 h60
  text "NONE" at 12709.96,966.64 h60
  text "X" at 13044.46,966.64 h60
  text "PER ORDER" at 13763.46,966.64 h60
  text ".Layer_Name" at 577,-858.49 h60
M11 Gerber Information:
  lines w10: -292,-930.17 6308,-930.17 ; -292,-726.83 6310,-726.83 ; -292,-523.5 -292,-1133.5 3713,-1133.5 6310,-1133.5 6310,-523.5 -291.5,-523.5 -291.5,-1133.5 1284,-1133.5 ; 2173,-1133.5 2173,-523.5 ; 3440,-726.83 3440,-523.5 ; 4280,-726.83 4280,-523.5 ; 4902,-1140 4902,-937.17
  text "ALL ARTWORK VIEWED FROM TOP SIDE" at -228.5,-655.67 h60
  text "BOARD #:" at 2248,-655.67 h60
  text ".PRJ_Number" at 2793.5,-655.67 h60
  text "REV:" at 3638,-655.67 h60
  text ".PCB_Rev" at 3929.5,-655.67 h60
  text "SVN REV:" at 4476,-655.67 h60
  text ".VersionControl_RevNumber" at 4982,-655.67 h60
  text "LAYER NAME =" at -228.5,-858.49 h60
  text "TID #:" at 2248,-859 h60
  text ".TID" at 2793.5,-859 h60
  text "PLOT NAME =" at -228.5,-1064.34 h60
  text ".plot_File_Name" at 577,-1064.34 h60
  text "GENERATED    :" at 2250,-1064.34 h60
  text ".Print_Date" at 3119.5,-1064.34 h60
  text ".Print_Time" at 3848.5,-1064.34 h60
  text "TEXAS INSTRUMENTS" at 5113,-1064.34 h60
M12 Stackup:
  drawing of 191 lines, arcs and shapes, not listed
  text "Layer" at 9790.34,7830 h60
  text "Name" at 10200.26,7830 h60
  text "Material" at 11130,7830 h60
  text "Thickness" at 11989.77,7830 h60
  text "Constant" at 12639.6,7830 h60
  text "Board Layer Stack" at 13209.46,7830 h60
  text "1" at 9790.34,7710 h60
  text "Top Overlay" at 10200.26,7710 h60
  text "2" at 9790.34,7590 h60
  text "Top Solder" at 10200.26,7590 h60
  text "Solder Resist" at 11130,7590 h60
  text "0.40mil" at 11989.77,7590 h60
  text "3.5" at 12639.6,7590 h60
  text "3" at 9790.34,7470 h60
  text "Top Layer" at 10200.26,7470 h60
  text "Copper" at 11130,7470 h60
  text "1.40mil" at 11989.77,7470 h60
  text "4" at 9790.34,7350 h60
  text "Dielectric1" at 10200.26,7350 h60
  text "FR-4" at 11130,7350 h60
  text "59.20mil" at 11989.77,7350 h60
  text "4.8" at 12639.6,7350 h60
  text "5" at 9790.34,7230 h60
  text "Bottom Layer" at 10200.26,7230 h60
  text "Copper" at 11130,7230 h60
  text "1.40mil" at 11989.77,7230 h60
  text "6" at 9790.34,7110 h60
  text "Bottom Solder" at 10200.26,7110 h60
  text "Solder Resist" at 11130,7110 h60
  text "0.40mil" at 11989.77,7110 h60
  text "3.5" at 12639.6,7110 h60
  text "7" at 9790.34,6990 h60
  text "Bottom Overlay" at 10200.26,6990 h60
  text ".Layer_Name" at 577,-858.49 h60
M13 Component Bodies Top:
  text ".Layer_Name" at 577,-858.49 h60
M14 Component Bodies Bottom:
  text ".Layer_Name" at 577,-858.49 h60
M15 Courtyards Top:
  text ".Layer_Name" at 577,-858.49 h60
M16 Courtyards Bottom:
  text ".Layer_Name" at 577,-858.49 h60
Drill Drawing:
  text ".Layer_Name" at 577,-858.49 h60
M17 Embedded Cavity:
  text ".Layer_Name" at 577,-858.49 h60
M18 Embedded Assembly:
  text ".Layer_Name" at 577,-858.49 h60
M19 Embedded Keepout:
  text ".Layer_Name" at 577,-858.49 h60

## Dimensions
0,0 to 1900,0 on M2 Board Dimensions
0,-400 to 1000,-400 on M2 Board Dimensions
0,0 to 1900.05,1702.81 on M2 Board Dimensions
